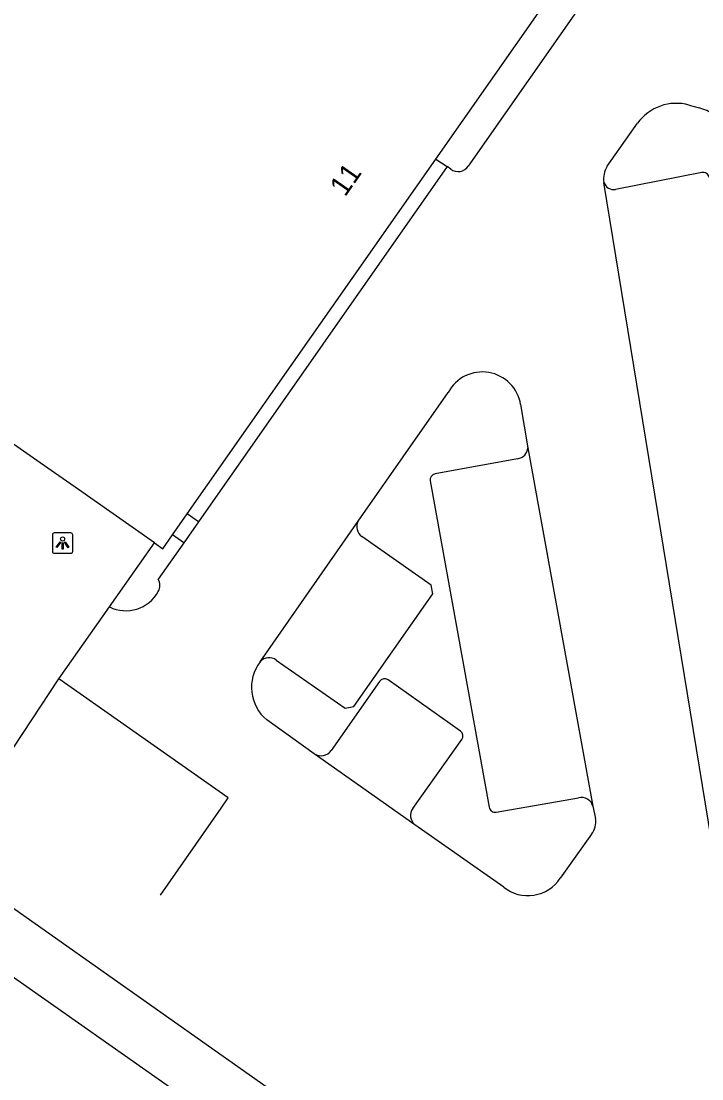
# Model space of a CAD drawing. Extents: x 152881 to 155736, y 382924 to 386919.
# Drawn here: x 155175.3 to 155208.5, y 385255.6 to 385307.3 of the extents above; entities that cross this region are included whole.
import ezdxf

# ---------------------------------------------------------------- set-up
doc = ezdxf.new("R2010")
doc.units = 0
for name, color, linetype in [('IMGEO_Grasland_overig', 7, 'Continuous'), ('IMGEO_Hek', 7, 'Continuous'), ('IMGEO_Lichtpunt', 7, 'Continuous'), ('IMGEO_Pand', 7, 'Continuous'), ('IMGEO_Pand_nummerreeks', 7, 'Continuous'), ('IMGEO_Parkeervlak_open', 7, 'Continuous'), ('IMGEO_Rijbaan_lokaal_gesloten', 7, 'Continuous'), ('IMGEO_Rijbaan_lokaal_open', 7, 'Continuous'), ('IMGEO_Voetpad_open', 7, 'Continuous')]:
    doc.layers.add(name, color=color, linetype=linetype)

msp = doc.modelspace()

# ---------------------------------------------------------------- linework, layer by layer
at = {"layer": 'IMGEO_Grasland_overig'}
msp.add_lwpolyline([(155179.578, 385278.667), (155181.779, 385281.796)], dxfattribs=at)
at = {"layer": 'IMGEO_Hek'}
for points in [[(155179.578, 385278.667), (155181.779, 385281.796)], [(155177.103, 385275.146), (155179.578, 385278.667)], [(155185.038, 385268.836), (155185.386, 385269.336), (155177.103, 385275.146)], [(155182.069, 385264.57), (155185.038, 385268.836)]]:
    msp.add_lwpolyline(points, dxfattribs=at)
at = {"layer": 'IMGEO_Lichtpunt'}
for p, q in [((155177.695, 385282.283), (155176.887, 385282.283)), ((155177.695, 385282.283), (155176.887, 385282.283)), ((155176.793, 385282.188), (155176.793, 385281.381)), ((155176.793, 385282.188), (155176.793, 385281.381)), ((155177.789, 385281.381), (155177.789, 385282.188)), ((155177.789, 385281.381), (155177.789, 385282.188)), ((155176.887, 385281.287), (155177.695, 385281.287)), ((155176.887, 385281.287), (155177.695, 385281.287))]:
    msp.add_line(p, q, dxfattribs=at)
for points in [[(155177.167, 385281.852), (155177.206, 385281.824), (155177.018, 385281.562), (155176.98, 385281.589), (155177.167, 385281.852)], [(155177.269, 385281.804), (155177.316, 385281.804), (155177.316, 385281.482), (155177.269, 385281.482), (155177.269, 385281.804)], [(155177.379, 385281.824), (155177.417, 385281.851), (155177.604, 385281.589), (155177.565, 385281.561), (155177.379, 385281.824)]]:
    msp.add_lwpolyline(points, dxfattribs=at)
msp.add_circle((155177.292, 385281.986), 0.0994, dxfattribs=at)
for centre, start, end in [((155176.887, 385282.188), 90, 180), ((155176.887, 385282.188), 90, 180), ((155177.695, 385282.188), 0, 90), ((155177.695, 385282.188), 0, 90), ((155176.887, 385281.381), 180, 270), ((155176.887, 385281.381), 180, 270), ((155177.695, 385281.381), 270, 0), ((155177.695, 385281.381), 270, 360)]:
    msp.add_arc(centre, 0.0946, start, end, dxfattribs=at)
at = {"layer": 'IMGEO_Pand'}
for points in [[(155181.779, 385281.796), (155177.899, 385284.513), (155176.9, 385285.213), (155174.357, 385286.994), (155161.287, 385296.148), (155184.252, 385328.925), (155196.646, 385320.245), (155197.52, 385319.633), (155204.941, 385314.436)], [(155195.531, 385300.557), (155202.214, 385310.095), (155205.152, 385314.288), (155204.941, 385314.436)], [(155183.379, 385283.214), (155195.531, 385300.557)], [(155182.664, 385282.193), (155183.379, 385283.214)], [(155181.779, 385281.796), (155182.186, 385281.511), (155182.664, 385282.193)]]:
    msp.add_lwpolyline(points, dxfattribs=at)
at = {"layer": 'IMGEO_Parkeervlak_open'}
for points in [[(155208.534, 385299.896), (155204.32, 385299.072)], [(155199.522, 385285.908), (155195.501, 385285.168)], [(155195.26, 385284.82), (155198.14, 385268.873)], [(155187.737, 385276.069), (155191.096, 385273.722), (155191.521, 385273.805), (155195.384, 385279.307), (155195.31, 385279.735), (155191.917, 385282.103)], [(155196.731, 385272.596), (155193.2, 385275.095)], [(155192.781, 385275.022), (155190.419, 385271.648)], [(155194.409, 385268.82), (155196.802, 385272.177)], [(155198.487, 385268.631), (155202.509, 385269.34)]]:
    msp.add_lwpolyline(points, dxfattribs=at)
for centre, radius, start, end in [((155208.591, 385299.601), 0.301, 10.3787, 100.9771), ((155204.223, 385299.561), 0.499, 198.0239, 281.2642), ((155199.456, 385286.487), 0.583, 276.5171, 355.3433), ((155195.556, 385284.873), 0.3, 100.4911, 190.1015), ((155192.259, 385282.586), 0.592, 152.3682, 234.669), ((155187.385, 385275.592), 0.593, 53.5582, 137.9631), ((155193.027, 385274.848), 0.301, 54.9788, 144.7875), ((155196.556, 385272.351), 0.301, 324.7593, 54.4756), ((155189.927, 385271.991), 0.6, 236.3439, 325.0969), ((155202.644, 385268.771), 0.584, 15.7435, 103.3254), ((155194.882, 385268.476), 0.585, 143.9622, 230.8883), ((155198.434, 385268.925), 0.298, 189.9565, 280.2592)]:
    msp.add_arc(centre, radius, start, end, dxfattribs=at)
at = {"layer": 'IMGEO_Rijbaan_lokaal_gesloten'}
msp.add_lwpolyline([(155169.826, 385264.115), (155197.654, 385244.57)], dxfattribs=at)
at = {"layer": 'IMGEO_Rijbaan_lokaal_open'}
for points in [[(155203.096, 385308.755), (155197.119, 385300.213)], [(155207.909, 385303.193), (155208.396, 385303.062)], [(155203.913, 385300.205), (155205.394, 385302.307)], [(155196.08, 385300.186), (155183.934, 385282.825)], [(155196.262, 385300.058), (155196.08, 385300.186)], [(155209.44, 385264.557), (155203.748, 385299.407)], [(155191.735, 385282.86), (155196.136, 385289.152)], [(155199.678, 385288.556), (155200.037, 385286.44)], [(155200.037, 385286.44), (155203.206, 385268.93)], [(155183.934, 385282.825), (155183.219, 385281.804)], [(155186.944, 385275.989), (155191.735, 385282.86)], [(155183.219, 385281.804), (155181.96, 385280.02)], [(155171.343, 385266.414), (155177.103, 385275.146), (155179.578, 385278.667)], [(155189.595, 385271.492), (155187.277, 385273.143)], [(155194.513, 385268.022), (155189.595, 385271.492)], [(155203.206, 385268.93), (155203.331, 385268.321)], [(155198.85, 385264.964), (155194.513, 385268.022)], [(155203.147, 385267.562), (155201.615, 385265.405)], [(155199.195, 385246.776), (155171.343, 385266.414)]]:
    msp.add_lwpolyline(points, dxfattribs=at)
for centre, radius, start, end in [((155207.283, 385300.956), 2.323, 74.3735, 144.4398), ((155207.605, 385300.339), 2.836, 10.4022, 73.8038), ((155196.616, 385300.548), 0.604, 234.1332, 326.3705), ((155204.832, 385299.599), 1.101, 146.6006, 190.0349), ((155197.806, 385288.254), 1.896, 9.1571, 151.7399), ((155181.471, 385279.714), 0.577, 329.6573, 32.0672), ((155180.382, 385280.284), 1.806, 243.5634, 331.4855), ((155188.582, 385274.738), 2.061, 142.6368, 230.7104), ((155202.401, 385268.145), 0.947, 322.0127, 10.7333), ((155200.03, 385266.454), 1.901, 231.6228, 326.5012)]:
    msp.add_arc(centre, radius, start, end, dxfattribs=at)
at = {"layer": 'IMGEO_Voetpad_open'}
for points in [[(155195.531, 385300.557), (155196.08, 385300.186)], [(155183.934, 385282.825), (155183.379, 385283.214)], [(155183.219, 385281.804), (155182.664, 385282.193)]]:
    msp.add_lwpolyline(points, dxfattribs=at)

# ---------------------------------------------------------------- texts
at = {"layer": 'IMGEO_Pand_nummerreeks'}
msp.add_text('11', height=1, rotation=55.0658, dxfattribs=at).set_placement((155191.098, 385298.673))

doc.saveas('drawing.dxf')
